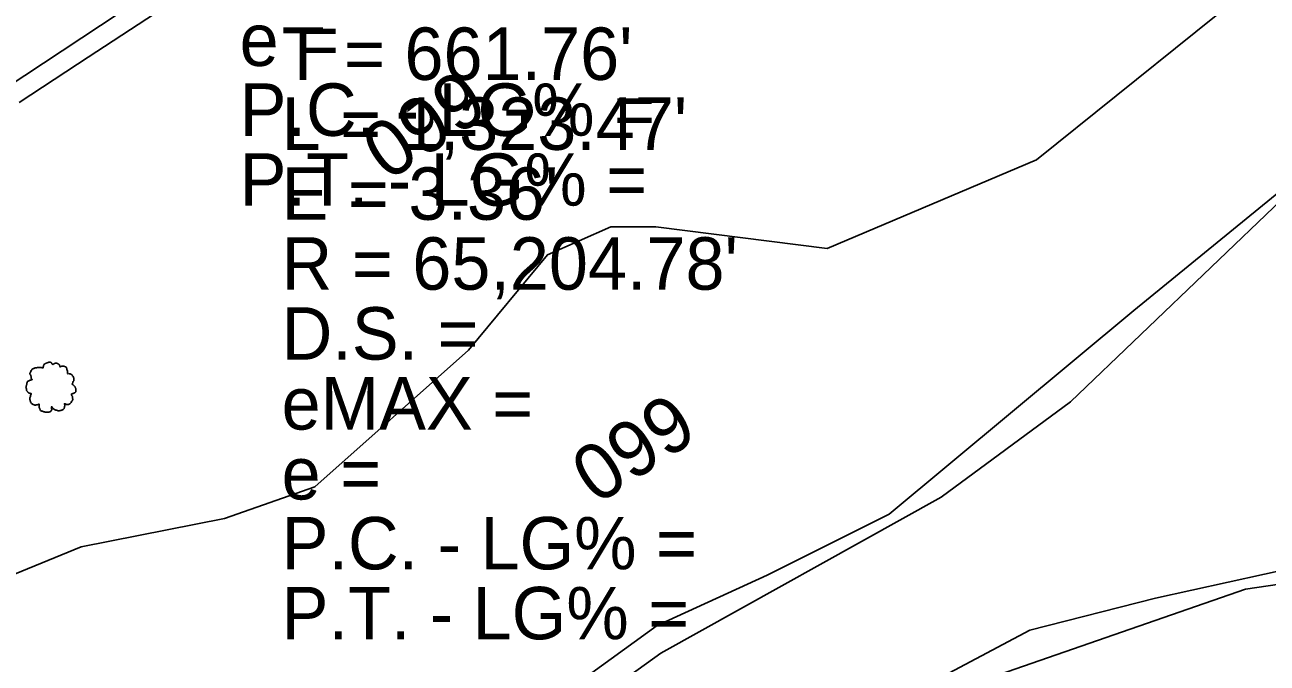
# Model space of a CAD drawing. Extents: x 1901471 to 1963503, y 756461 to 799997.
# Drawn here: x 1916709.3 to 1916886.8, y 764813.6 to 764904.9 of the extents above; entities that cross this region are included whole.
import ezdxf

# ---------------------------------------------------------------- set-up
doc = ezdxf.new("R2010")
doc.units = 0
for name, color, linetype in [('RD_DTM_BkLn1', 7, 'Continuous'), ('RD_EX_Road', 7, 'Continuous'), ('RD_EX_VEG', 7, 'Continuous'), ('RD_HC_Cl', 7, 'Continuous'), ('RD_HC_Data', 7, 'Continuous'), ('RD_HC_TX_Sta50', 7, 'Continuous')]:
    doc.layers.add(name, color=color, linetype=linetype)

# ---------------------------------------------------------------- blocks, each defined once
blk = doc.blocks.new('T2')
at = {"layer": 'RD_EX_VEG'}
for points in [[(0.05233333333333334, 7.213166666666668), (-0.24750000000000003, 7.238166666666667), (-0.5723333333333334, 7.138166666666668), (-0.8222500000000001, 7.038250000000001), (-1.0471666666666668, 6.963250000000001), (-1.2720833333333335, 6.863250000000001), (-1.5719166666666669, 6.688416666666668), (-1.7968333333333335, 6.488416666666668), (-1.9218333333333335, 6.2385833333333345), (-1.9718333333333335, 6.013666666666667), (-2.0217500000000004, 5.738833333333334), (-2.0217500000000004, 5.563833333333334), (-2.146666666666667, 5.538833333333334), (-2.296666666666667, 5.563833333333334), (-2.5465000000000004, 5.638833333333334), (-2.796416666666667, 5.638833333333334), (-3.0463333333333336, 5.638833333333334), (-3.3961666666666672, 5.613833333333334), (-3.7460000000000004, 5.613833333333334), (-4.020833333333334, 5.563833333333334), (-4.345750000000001, 5.513916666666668), (-4.720583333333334, 5.389000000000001), (-5.0704166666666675, 5.264000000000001), (-5.37025, 5.014083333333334), (-5.620166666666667, 4.539333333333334), (-5.745166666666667, 4.189500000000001), (-5.895083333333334, 3.9395833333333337), (-5.745166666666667, 3.489833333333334), (-5.570166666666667, 3.139916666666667), (-5.545250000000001, 2.9400000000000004), (-5.470250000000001, 2.5152500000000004), (-5.37025, 2.2903333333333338), (-5.245333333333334, 2.0903333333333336), (-5.320250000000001, 2.065416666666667), (-5.695166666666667, 2.015416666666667), (-5.995000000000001, 1.9155000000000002), (-6.419833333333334, 1.6905833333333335), (-6.644750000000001, 1.465666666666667), (-6.744750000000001, 1.1407500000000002), (-6.769666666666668, 0.7909166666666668), (-6.869583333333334, 0.5910833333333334), (-6.944583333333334, 0.3161666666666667), (-6.969583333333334, 0.2411666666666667), (-7.019583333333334, -0.08366666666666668), (-6.9195833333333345, -0.5335000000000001), (-6.894583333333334, -0.8833333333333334), (-6.769666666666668, -1.1082500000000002), (-6.619750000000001, -1.2830833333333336), (-6.444833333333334, -1.5330000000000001), (-6.045000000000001, -1.7579166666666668), (-5.7201666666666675, -1.8579166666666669), (-5.520250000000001, -1.8828333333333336), (-5.695166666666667, -2.382666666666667), (-5.745166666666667, -2.7325000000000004), (-5.870083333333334, -3.132333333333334), (-5.870083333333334, -3.2072500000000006), (-5.920000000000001, -3.682083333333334), (-5.770166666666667, -4.007000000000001), (-5.695166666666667, -4.38175), (-5.520250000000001, -4.606666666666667), (-5.245333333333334, -4.906583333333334), (-4.9205000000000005, -5.131416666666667), (-4.420666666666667, -5.256416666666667), (-4.020833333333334, -5.231416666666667), (-3.4460833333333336, -5.056500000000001), (-3.1962500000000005, -4.9815000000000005), (-3.2212500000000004, -5.156416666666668), (-3.1962500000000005, -5.531333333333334), (-3.1962500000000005, -5.956083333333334), (-3.0463333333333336, -6.280916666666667), (-2.946333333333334, -6.555833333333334), (-2.796416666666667, -6.805750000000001), (-2.4715000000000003, -7.030583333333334), (-2.07175, -7.1055833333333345), (-1.6469166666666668, -7.2555000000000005), (-1.1970833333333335, -7.330500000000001), (-0.6973333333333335, -7.355500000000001), (-0.09758333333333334, -7.205583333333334), (0.17725000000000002, -7.080583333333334), (0.27725000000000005, -6.905666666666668), (0.47716666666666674, -6.530833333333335), (0.4271666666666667, -6.3059166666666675), (0.4521666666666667, -5.706166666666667), (0.5520833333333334, -5.881166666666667), (0.7270833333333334, -6.231000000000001), (1.2268333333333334, -6.530833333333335), (1.626666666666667, -6.705750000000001), (2.101416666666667, -6.8557500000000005), (2.4013333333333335, -6.930666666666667), (2.8760833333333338, -6.8557500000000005), (3.2510000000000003, -6.780750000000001), (3.6257500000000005, -6.655750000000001), (3.9256666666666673, -6.380916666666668), (4.100583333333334, -6.106000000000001), (4.1505833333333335, -5.831166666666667), (4.2255, -5.456333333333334), (4.275500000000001, -5.281416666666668)], [(4.275500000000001, -5.281416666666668), (4.200583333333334, -5.106416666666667), (4.1505833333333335, -4.856583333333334), (4.2255, -4.881583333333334), (4.4004166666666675, -4.931583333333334), (4.675333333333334, -5.056500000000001), (4.900250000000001, -5.131416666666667), (5.225083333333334, -5.106416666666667), (5.500000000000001, -5.006500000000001), (5.949750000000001, -4.731583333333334), (6.224666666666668, -4.256833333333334), (6.499500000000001, -3.8570000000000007), (6.5745000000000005, -3.5321666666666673), (6.524500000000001, -3.3072500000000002), (6.499500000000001, -2.8075000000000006), (6.299583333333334, -2.5575833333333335), (6.249583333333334, -2.432666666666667), (6.1496666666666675, -2.0328333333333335), (6.224666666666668, -1.9828333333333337), (6.499500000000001, -1.9328333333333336), (6.874333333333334, -1.8079166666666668), (7.149250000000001, -1.6830000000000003), (7.374166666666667, -1.5080000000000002), (7.449083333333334, -1.2830833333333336), (7.424166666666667, -0.8833333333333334), (7.4740833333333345, -0.48350000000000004), (7.399166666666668, -0.3335), (7.299166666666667, -0.1836666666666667), (7.224166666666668, 0.016333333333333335), (7.074250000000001, 0.16616666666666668), (6.974333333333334, 0.3161666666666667), (6.874333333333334, 0.41608333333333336), (6.749416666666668, 0.5660833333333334), (6.5745000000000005, 0.6910000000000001), (6.424583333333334, 0.7410000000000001), (6.374583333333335, 0.8909166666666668), (6.524500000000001, 1.0908333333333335), (6.5745000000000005, 1.1907500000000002), (6.599416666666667, 1.4156666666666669), (6.824416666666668, 1.7655000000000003), (6.874333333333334, 2.1653333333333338), (6.824416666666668, 2.590166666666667), (6.774416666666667, 2.8650833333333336), (6.624416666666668, 3.139916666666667), (6.424583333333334, 3.3898333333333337), (6.299583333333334, 3.5647500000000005), (6.124666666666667, 3.689666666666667), (5.799833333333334, 3.814666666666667), (5.549916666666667, 3.864583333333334), (5.200083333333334, 3.864583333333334), (5.000166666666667, 3.9145833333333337), (5.025166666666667, 3.964583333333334), (5.025166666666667, 4.1145000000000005), (5.025166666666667, 4.389416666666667), (4.950166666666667, 4.839166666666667), (4.800250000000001, 5.339), (4.800250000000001, 5.364000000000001), (4.7002500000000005, 5.613833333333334), (4.475416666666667, 5.813750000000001), (4.3005, 5.913666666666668), (4.100583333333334, 6.038666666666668), (3.850666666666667, 6.063666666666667), (3.5508333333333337, 6.063666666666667), (3.2759166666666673, 6.013666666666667), (3.0760000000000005, 5.913666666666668), (2.9010833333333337, 5.788750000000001), (2.8260833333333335, 5.938666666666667), (2.726166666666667, 6.2385833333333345), (2.676166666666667, 6.3885000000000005), (2.52625, 6.563416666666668), (2.301416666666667, 6.7633333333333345), (1.8515000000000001, 6.888250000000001), (1.2268333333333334, 6.813333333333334), (0.9269166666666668, 6.613416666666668), (0.7770000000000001, 6.438500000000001), (0.7270833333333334, 6.563416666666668), (0.5270833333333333, 6.7633333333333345), (0.4271666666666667, 6.938250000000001), (0.25225000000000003, 7.063250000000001), (0.10233333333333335, 7.163166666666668), (0.0023333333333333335, 7.213166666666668)]]:
    blk.add_spline(points, degree=3, dxfattribs=at)

msp = doc.modelspace()

# ---------------------------------------------------------------- linework, layer by layer
at = {"layer": 'RD_DTM_BkLn1'}
msp.add_lwpolyline([(1916708.5128141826, 764893.7486122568), (1916716.8498088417, 764899.2672688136), (1916718.373893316, 764900.2761334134), (1916726.7503304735, 764905.7363251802), (1916735.1267676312, 764911.1965169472), (1916743.5032047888, 764916.656708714), (1916751.8796419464, 764922.116900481), (1916756.3112790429, 764925.005669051)], dxfattribs=at)
at = {"layer": 'RD_EX_Road'}
for points in [[(1917920.7000000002, 765683.7800000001), (1917827.6100000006, 765623.6000000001), (1917724.2700000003, 765556.8600000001), (1917629.7400000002, 765496.06), (1917551.6200000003, 765445.1100000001), (1917440.4900000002, 765373.4500000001), (1917340.4300000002, 765309.3700000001), (1917237.9100000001, 765243.0400000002), (1917140.5200000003, 765180.4000000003), (1917052.7600000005, 765122.8900000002), (1916953.7200000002, 765057.9900000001), (1916861.0400000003, 764997.2000000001), (1916799.9200000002, 764957.2300000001), (1916779.9200000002, 764944.4200000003), (1916660.2300000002, 764865.2000000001), (1916531.4700000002, 764780.5000000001), (1915851.1300000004, 764323.2900000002)], [(1916257.5100000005, 764424.5200000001), (1916375.3000000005, 764503.0100000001), (1916538.6500000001, 764609.06), (1916645.5000000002, 764680.6000000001), (1916799.9600000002, 764787.56), (1916814.4400000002, 764796.81), (1916832.9200000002, 764807.6900000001), (1916852.9200000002, 764818.33), (1916870.89, 764822.8800000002), (1916891.6500000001, 764827.4400000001), (1916915.1900000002, 764831.7400000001), (1916931.9000000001, 764834.0200000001), (1916940.2500000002, 764840.8600000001), (1916948.1000000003, 764853.3900000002), (1916953.6700000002, 764862.2500000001), (1916960.0000000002, 764876.1700000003), (1916954.4300000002, 764893.6300000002), (1916944.0500000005, 764902.4900000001), (1916950.1300000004, 764909.58), (1916976.9600000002, 764932.2400000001), (1917007.3400000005, 764956.2900000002), (1917041.5100000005, 764977.3), (1917092.14, 765007.0400000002)], [(1916180.5100000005, 764395.7000000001), (1916252.9600000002, 764442.5200000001), (1916365.2800000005, 764518.9500000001), (1916411.7500000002, 764550.5100000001), (1916477.3600000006, 764594.0200000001), (1916548.2200000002, 764641.3), (1916657.3500000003, 764713.6300000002), (1916698.8100000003, 764741.9900000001), (1916800.1900000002, 764815.0100000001), (1916840.2600000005, 764837.31), (1916858.7400000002, 764850.9800000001), (1916888.8700000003, 764879.8400000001), (1916911.14, 764890.7200000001), (1916919.7500000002, 764893.5100000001), (1916923.2900000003, 764893.7600000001), (1916924.0500000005, 764898.06), (1916917.7200000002, 764901.8600000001)]]:
    msp.add_lwpolyline(points, dxfattribs=at)
at = {"layer": 'RD_EX_VEG'}
for points in [[(1916697.4300000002, 764822.0900000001), (1916717.3600000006, 764830.2100000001), (1916737.8500000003, 764834.2700000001), (1916750.7600000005, 764838.7900000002), (1916772.7200000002, 764858.3500000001), (1916783.9800000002, 764872.0100000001), (1916793.0200000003, 764875.9800000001), (1916799.4800000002, 764875.9800000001), (1916823.9700000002, 764872.8900000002), (1916853.8400000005, 764885.55), (1916899.4100000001, 764922.2500000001), (1916965.7300000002, 764967.06), (1917011.0400000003, 764996.8), (1917059.14, 765027.1800000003), (1917101.1600000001, 765055.5300000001)], [(1917100.4000000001, 765023.7600000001), (1917054.8300000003, 764997.1800000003), (1917004.7100000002, 764965.9200000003), (1916967.7500000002, 764939.3400000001), (1916938.64, 764914.5300000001), (1916929.5300000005, 764909.3400000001), (1916918.39, 764904.2800000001), (1916912.5700000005, 764896.1800000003), (1916889.7900000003, 764882.0100000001), (1916867.7600000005, 764864.0300000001), (1916832.8300000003, 764834.9200000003), (1916815.3600000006, 764826.1900000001), (1916799.6700000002, 764818.9600000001), (1916738.7700000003, 764774.8500000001), (1916678.0600000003, 764735.1800000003)], [(1916701.6800000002, 764713.6800000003), (1916737.4800000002, 764741.9100000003), (1916768.6600000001, 764762.9500000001), (1916799.8500000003, 764782.2300000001), (1916841.4400000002, 764809.4800000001), (1916883.7100000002, 764824.1600000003), (1916926.4900000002, 764830.4900000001), (1916942.1900000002, 764838.0900000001), (1916961.6800000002, 764872.0100000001), (1916960.1600000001, 764888.2100000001), (1916947.7600000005, 764903.6500000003), (1916980.9200000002, 764933.7700000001), (1917028.5100000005, 764967.31), (1917103.9400000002, 765013.1300000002)]]:
    msp.add_lwpolyline(points, dxfattribs=at)
at = {"layer": 'RD_HC_Cl'}
for centre, radius, start, end in [((1948618.927154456, 716714.6838111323), 57895.907900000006, 122.84589019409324, 124.00882459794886), ((1948627.813986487, 716698.9149995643), 57883.94070000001, 122.84637793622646, 124.00852866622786), ((1952673.9465588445, 710531.7599155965), 65204.77830000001, 122.85416067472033, 124.0171003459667)]:
    msp.add_arc(centre, radius, start, end, dxfattribs=at)

# ---------------------------------------------------------------- block references
at = {"layer": 'RD_EX_VEG', "xscale": 0.4921259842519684, "yscale": 0.4921259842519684}
msp.add_blockref('T2', (1916712.9300000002, 764853.0900000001), dxfattribs=at)

# ---------------------------------------------------------------- texts
at = {"layer": 'RD_HC_Data'}
for s, p in [('e = ', (1916740.0000000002, 764899.0000000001)), ("T = 661.76'", (1916746.0000000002, 764897.0000000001)), ('P.C. - LG% = ', (1916740.0000000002, 764889.0000000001)), ("L = 1,323.47'", (1916746.0000000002, 764887.0000000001)), ('P.T. - LG% = ', (1916740.0000000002, 764879.0000000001)), ("E = 3.36'", (1916746.0000000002, 764877.0000000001)), ("R = 65,204.78'", (1916746.0000000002, 764867.0000000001)), ('D.S. = ', (1916746.0000000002, 764857.0000000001)), ('eMAX = ', (1916746.0000000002, 764847.0000000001)), ('e = ', (1916746.0000000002, 764837.0000000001)), ('P.C. - LG% = ', (1916746.0000000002, 764827.0000000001)), ('P.T. - LG% = ', (1916746.0000000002, 764817.0000000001))]:
    msp.add_text(s, height=7.500000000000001, dxfattribs=at).set_placement(p)
at = {"layer": 'RD_HC_TX_Sta50'}
for rotation, p in [(213.4700772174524, (1916771.5866746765, 764898.916882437)), (213.44769819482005, (1916801.4812941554, 764852.6293596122))]:
    msp.add_text('660', height=8.000000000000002, rotation=rotation, dxfattribs=at).set_placement(p)

doc.saveas('drawing.dxf')
